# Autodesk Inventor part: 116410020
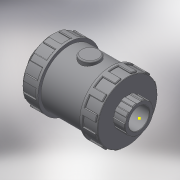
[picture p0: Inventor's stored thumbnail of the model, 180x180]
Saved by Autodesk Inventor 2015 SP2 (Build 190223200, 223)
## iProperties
Created: 2017-11
Part Number: 116410020
Material: Generic
Description: PLASSON FOOT VALVE THR PVC 2"
Document SubType Name: Modeling
Designer: KIM
Density: 1 g/cm^3
Appearance: Default
Author: KIM
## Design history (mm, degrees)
derived "116410 - 116010.ipt"
feature "Solid1::116410 - 116010.ipt"
tag "TaggingFeature1"
body "Solid1"
other parameters: "d0" = 169, "d1" = 56.656, "d2" = 118, "d3" = 26, "d4" = 45.3248, "d5" = 18.2, "d7" = 79.3184, "d8" = 106.2, "d13" = 1.69968, "d23" = 26, "d24" = 113.28, "d25" = 1.13312, "d26" = 1.69968, "d27" = 17.7, "d28" = 8.85, "d29" = 19.5, "d30" = 0, "d35" = 1.69968, "d39" = 59, "d45" = 360 deg, "d47" = 1.13312, "d50" = 59, "d51" = 35.4, "d53" = 0, "d54" = 2.36, "d55" = 11.3312, "d56" = 5.6656, "d58" = 0, "d59" = 1.69968, "d61" = 360 deg, "G_" = 56.656, "l_" = 26, "H_" = 169, "K_" = 118
